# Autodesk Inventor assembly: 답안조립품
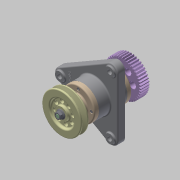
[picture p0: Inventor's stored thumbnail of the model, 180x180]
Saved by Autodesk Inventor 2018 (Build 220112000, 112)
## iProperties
Created: 2023-04
Part Number: 답안조립품
Material: 일반
Document SubType Name: Assembly
Designer: home
Author: home
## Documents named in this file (11)
- C:\Users\home\Desktop\730407V1004\답안조립품.iam
- C:\Users\home\Desktop\730407V1004\본체.ipt
- C:\Users\home\Desktop\730407V1004\베어링 6204.ipt
- C:\Users\home\Desktop\730407V1004\축.ipt
- C:\Users\home\Desktop\730407V1004\커버.ipt
- C:\Users\home\Desktop\730407V1004\오일 실 20 32 8.ipt
- C:\Users\home\Desktop\730407V1004\볼트 M4 x 12.ipt
- C:\Users\home\Desktop\730407V1004\묻힘키 5x5x16.ipt
- C:\Users\home\Desktop\730407V1004\v-벨트풀리.ipt
- C:\Users\home\Desktop\730407V1004\스퍼기어.ipt
- C:\Users\home\Desktop\730407V1004\6각 플랜지 너트 M10.ipt
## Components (3 placed, 2 different names)
1. v-벨트풀리:1
2. 6각 플랜지 너트 M10:1
3. 6각 플랜지 너트 M10:2
